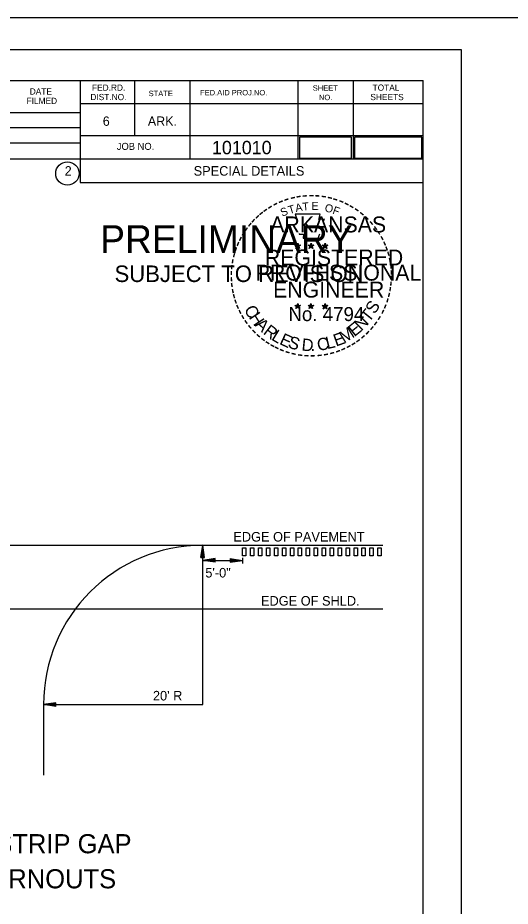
# Model space of a CAD drawing. Extents: x 3575 to 11445, y 9479 to 13278.
# Drawn here: x 8971 to 9280, y 10549 to 11106 of the extents above; entities that cross this region are included whole.
import ezdxf

# ---------------------------------------------------------------- set-up
doc = ezdxf.new("R2010")
doc.units = 0
for name, color, linetype in [('Page Number', 7, 'Continuous'), ('R_Dimension', 7, 'Continuous'), ('R_NoPlot', 7, 'Continuous'), ('STAMP_PE_CRAFTON-SIGNATURE', 7, 'Continuous'), ('STAMP_PE_FOSTER-SIGNATURE', 7, 'Continuous'), ('STAMP_PE_SEAL-INFO', 7, 'Continuous'), ('STAMP_PE_TAEGTMEYER', 7, 'Continuous'), ('STAMP_PRELIMINARY', 7, 'Continuous'), ('Total_Pages', 7, 'Continuous')]:
    doc.layers.add(name, color=color, linetype=linetype)

msp = doc.modelspace()

# ---------------------------------------------------------------- linework, layer by layer
at = {"layer": 'Page Number'}
msp.add_lwpolyline([(9147.9, 11018.05), (9180.55, 11018.05), (9180.55, 11031.25), (9147.9, 11031.25)], close=True, dxfattribs=at)
at = {"layer": 'R_Dimension'}
for p, q in [((9085.94, 10767.34), (9087.1, 10775.08)), ((9085.94, 10767.34), (9087.1, 10775.08)), ((9086.14, 10767.34), (9087.1, 10773.79)), ((9086.14, 10767.34), (9087.1, 10773.79)), ((9088.27, 10767.34), (9087.1, 10775.08)), ((9088.27, 10767.34), (9087.1, 10775.08)), ((9088.07, 10767.34), (9087.1, 10773.79)), ((9088.07, 10767.34), (9087.1, 10773.79)), ((9085.94, 10767.34), (9088.27, 10767.34)), ((9085.94, 10767.34), (9088.27, 10767.34)), ((9086.33, 10767.34), (9087.1, 10772.45)), ((9086.33, 10767.34), (9087.1, 10772.45)), ((9086.53, 10767.34), (9087.1, 10771.17)), ((9086.53, 10767.34), (9087.1, 10771.17)), ((9086.73, 10767.34), (9087.1, 10769.85)), ((9086.73, 10767.34), (9087.1, 10769.85)), ((9086.92, 10767.34), (9087.1, 10768.56)), ((9086.92, 10767.34), (9087.1, 10768.56)), ((9087.87, 10767.34), (9087.1, 10772.45)), ((9087.87, 10767.34), (9087.1, 10772.45)), ((9087.68, 10767.34), (9087.1, 10771.17)), ((9087.68, 10767.34), (9087.1, 10771.17)), ((9087.48, 10767.34), (9087.1, 10769.85)), ((9087.48, 10767.34), (9087.1, 10769.85)), ((9087.29, 10767.34), (9087.1, 10768.56)), ((9087.29, 10767.34), (9087.1, 10768.56)), ((9094.85, 10766.7), (9087.1, 10765.54)), ((9094.85, 10764.38), (9087.1, 10765.54)), ((9094.85, 10766.51), (9088.4, 10765.54)), ((9094.85, 10764.57), (9088.4, 10765.54)), ((9094.85, 10766.31), (9089.73, 10765.54)), ((9094.85, 10764.77), (9089.73, 10765.54)), ((9094.85, 10766.12), (9091.02, 10765.54)), ((9094.85, 10764.96), (9091.02, 10765.54)), ((9094.85, 10765.92), (9092.33, 10765.54)), ((9094.85, 10765.16), (9092.33, 10765.54)), ((9094.85, 10765.72), (9093.62, 10765.54)), ((9094.85, 10765.36), (9093.62, 10765.54)), ((9094.85, 10764.38), (9094.85, 10766.7)), ((9104.36, 10766.7), (9112.1, 10765.54)), ((9104.36, 10766.7), (9104.36, 10764.38)), ((9104.36, 10766.51), (9110.81, 10765.54)), ((9104.36, 10766.31), (9109.48, 10765.54)), ((9104.36, 10766.12), (9108.19, 10765.54)), ((9104.36, 10765.91), (9106.88, 10765.54)), ((9104.36, 10765.72), (9105.58, 10765.54)), ((9104.36, 10764.38), (9112.1, 10765.54)), ((9104.36, 10765.16), (9106.88, 10765.54)), ((9104.36, 10764.77), (9109.48, 10765.54)), ((9104.36, 10764.57), (9110.81, 10765.54)), ((9104.36, 10764.96), (9108.19, 10765.54)), ((9104.36, 10765.36), (9105.58, 10765.54)), ((8994.83, 10676.23), (8987.09, 10675.06)), ((8994.83, 10676.23), (8987.09, 10675.06)), ((8994.83, 10673.9), (8987.09, 10675.06)), ((8994.83, 10673.9), (8987.09, 10675.06)), ((8994.83, 10676.03), (8988.38, 10675.06)), ((8994.83, 10676.03), (8988.38, 10675.06)), ((8994.83, 10674.1), (8988.38, 10675.06)), ((8994.83, 10674.1), (8988.38, 10675.06)), ((8994.83, 10675.84), (8989.71, 10675.06)), ((8994.83, 10675.84), (8989.71, 10675.06)), ((8994.83, 10674.29), (8989.71, 10675.06)), ((8994.83, 10674.29), (8989.71, 10675.06)), ((8994.83, 10675.64), (8991, 10675.06)), ((8994.83, 10675.64), (8991, 10675.06)), ((8994.83, 10674.49), (8991, 10675.06)), ((8994.83, 10674.49), (8991, 10675.06)), ((8994.83, 10675.44), (8992.32, 10675.06)), ((8994.83, 10675.44), (8992.32, 10675.06)), ((8994.83, 10674.69), (8992.32, 10675.06)), ((8994.83, 10674.69), (8992.32, 10675.06)), ((8994.83, 10675.25), (8993.61, 10675.06)), ((8994.83, 10675.25), (8993.61, 10675.06)), ((8994.83, 10674.88), (8993.61, 10675.06)), ((8994.83, 10674.88), (8993.61, 10675.06)), ((8994.83, 10673.9), (8994.83, 10676.23)), ((8994.83, 10673.9), (8994.83, 10676.23))]:
    msp.add_line(p, q, dxfattribs=at)
at = {"layer": 'R_NoPlot'}
msp.add_lwpolyline([(7582.64, 11086.17), (9249.34, 11086.17), (9249.34, 10019.49), (7582.64, 10019.49)], close=True, dxfattribs=at)
at = {"layer": 'STAMP_PE_CRAFTON-SIGNATURE'}
for p, q in [((8686.88, 10775.08), (9200.28, 10775.08)), ((9087.1, 10675.06), (9087.1, 10775.08)), ((9112.1, 10767.26), (9112.1, 10763.56)), ((9087.1, 10765.54), (9112.1, 10765.54)), ((8686.88, 10735.07), (9200.28, 10735.07)), ((8987.09, 10675.06), (8987.09, 10630.78)), ((8987.09, 10675.06), (9087.1, 10675.06))]:
    msp.add_line(p, q, dxfattribs=at)
for points in [[(9112.1, 10768.41), (9112.1, 10773.41), (9114.19, 10773.41), (9114.19, 10768.41), (9112.1, 10768.41)], [(9117.1, 10768.41), (9117.1, 10773.41), (9119.19, 10773.41), (9119.19, 10768.41), (9117.1, 10768.41)], [(9122.1, 10768.41), (9122.1, 10773.41), (9124.19, 10773.41), (9124.19, 10768.41), (9122.1, 10768.41)], [(9127.1, 10768.41), (9127.1, 10773.41), (9129.19, 10773.41), (9129.19, 10768.41), (9127.1, 10768.41)], [(9132.1, 10768.41), (9132.1, 10773.41), (9134.19, 10773.41), (9134.19, 10768.41), (9132.1, 10768.41)], [(9137.1, 10768.41), (9137.1, 10773.41), (9139.19, 10773.41), (9139.19, 10768.41), (9137.1, 10768.41)], [(9142.11, 10768.41), (9142.11, 10773.41), (9144.19, 10773.41), (9144.19, 10768.41), (9142.11, 10768.41)], [(9147.11, 10768.41), (9147.11, 10773.41), (9149.19, 10773.41), (9149.19, 10768.41), (9147.11, 10768.41)], [(9152.11, 10768.41), (9152.11, 10773.41), (9154.19, 10773.41), (9154.19, 10768.41), (9152.11, 10768.41)], [(9157.11, 10768.41), (9157.11, 10773.41), (9159.19, 10773.41), (9159.19, 10768.41), (9157.11, 10768.41)], [(9162.11, 10768.41), (9162.11, 10773.41), (9164.19, 10773.41), (9164.19, 10768.41), (9162.11, 10768.41)], [(9167.11, 10768.41), (9167.11, 10773.41), (9169.19, 10773.41), (9169.19, 10768.41), (9167.11, 10768.41)], [(9172.11, 10768.41), (9172.11, 10773.41), (9174.19, 10773.41), (9174.19, 10768.41), (9172.11, 10768.41)], [(9177.11, 10768.41), (9177.11, 10773.41), (9179.19, 10773.41), (9179.19, 10768.41), (9177.11, 10768.41)], [(9182.11, 10768.41), (9182.11, 10773.41), (9184.19, 10773.41), (9184.19, 10768.41), (9182.11, 10768.41)], [(9187.11, 10768.41), (9187.11, 10773.41), (9189.19, 10773.41), (9189.19, 10768.41), (9187.11, 10768.41)], [(9192.11, 10768.41), (9192.11, 10773.41), (9194.19, 10773.41), (9194.19, 10768.41), (9192.11, 10768.41)], [(9197.11, 10768.41), (9197.11, 10773.41), (9199.19, 10773.41), (9199.19, 10768.41), (9197.11, 10768.41)]]:
    msp.add_lwpolyline(points, dxfattribs=at)
msp.add_arc((9087.1, 10675.06), 100.02, 90, 180, dxfattribs=at)
at = {"layer": 'STAMP_PE_FOSTER-SIGNATURE'}
for p, q in [((9144.99, 10963.44), (9146.73, 10962.89)), ((9144.99, 10963.44), (9146.25, 10963.22)), ((9144.99, 10963.44), (9146.17, 10962.83)), ((9145.65, 10961.4), (9146.73, 10962.89)), ((9145.65, 10961.4), (9146.28, 10962.62)), ((9145.65, 10961.4), (9146.72, 10962.49)), ((9146.73, 10964.71), (9146.53, 10963.45)), ((9147.8, 10961.4), (9146.72, 10962.47)), ((9146.73, 10962.89), (9146.73, 10964.71)), ((9146.73, 10964.71), (9146.98, 10963.46)), ((9148.47, 10963.44), (9146.73, 10962.89)), ((9147.8, 10961.4), (9146.73, 10962.89)), ((9148.47, 10963.44), (9147.04, 10963.2)), ((9147.8, 10961.4), (9147.11, 10962.86)), ((9148.47, 10963.44), (9147.45, 10962.93)), ((9153.34, 10963.44), (9155.08, 10962.89)), ((9153.34, 10963.44), (9154.6, 10963.22)), ((9153.34, 10963.44), (9154.52, 10962.83)), ((9154, 10961.4), (9155.08, 10962.89)), ((9154, 10961.4), (9154.63, 10962.62)), ((9154, 10961.4), (9155.07, 10962.49)), ((9155.08, 10964.71), (9154.88, 10963.45)), ((9156.15, 10961.4), (9155.07, 10962.47)), ((9155.08, 10962.89), (9155.08, 10964.71)), ((9155.08, 10964.71), (9155.33, 10963.46)), ((9156.82, 10963.44), (9155.08, 10962.89)), ((9156.15, 10961.4), (9155.08, 10962.89)), ((9156.82, 10963.44), (9155.39, 10963.2)), ((9156.15, 10961.4), (9155.46, 10962.86)), ((9156.82, 10963.44), (9155.8, 10962.93)), ((9162.16, 10963.38), (9163.9, 10962.83)), ((9162.16, 10963.38), (9163.42, 10963.16)), ((9162.16, 10963.38), (9163.34, 10962.77)), ((9162.82, 10961.34), (9163.9, 10962.83)), ((9162.82, 10961.34), (9163.45, 10962.56)), ((9162.82, 10961.34), (9163.89, 10962.43)), ((9163.9, 10964.65), (9163.7, 10963.39)), ((9164.97, 10961.34), (9163.89, 10962.41)), ((9163.9, 10962.83), (9163.9, 10964.65)), ((9163.9, 10964.65), (9164.15, 10963.4)), ((9165.64, 10963.38), (9163.9, 10962.83)), ((9164.97, 10961.34), (9163.9, 10962.83)), ((9165.64, 10963.38), (9164.21, 10963.14)), ((9164.97, 10961.34), (9164.28, 10962.8)), ((9165.64, 10963.38), (9164.62, 10962.87)), ((9144.97, 10925.58), (9146.71, 10925.02)), ((9144.97, 10925.58), (9146.23, 10925.35)), ((9144.97, 10925.58), (9146.15, 10924.97)), ((9145.63, 10923.54), (9146.71, 10925.02)), ((9145.63, 10923.54), (9146.26, 10924.76)), ((9145.63, 10923.54), (9146.7, 10924.62)), ((9146.71, 10926.85), (9146.51, 10925.59)), ((9147.78, 10923.54), (9146.7, 10924.61)), ((9146.71, 10925.02), (9146.71, 10926.85)), ((9146.71, 10926.85), (9146.96, 10925.6)), ((9148.45, 10925.58), (9146.71, 10925.02)), ((9147.78, 10923.54), (9146.71, 10925.02)), ((9148.45, 10925.58), (9147.02, 10925.33)), ((9147.78, 10923.54), (9147.09, 10924.99)), ((9148.45, 10925.58), (9147.43, 10925.07)), ((9153.31, 10925.58), (9155.06, 10925.02)), ((9153.31, 10925.58), (9154.58, 10925.35)), ((9153.31, 10925.58), (9154.5, 10924.97)), ((9153.98, 10923.54), (9155.06, 10925.02)), ((9153.98, 10923.54), (9154.61, 10924.76)), ((9153.98, 10923.54), (9155.05, 10924.62)), ((9155.06, 10926.85), (9154.85, 10925.59)), ((9156.12, 10923.54), (9155.05, 10924.61)), ((9155.06, 10925.02), (9155.06, 10926.85)), ((9155.06, 10926.85), (9155.3, 10925.6)), ((9156.79, 10925.58), (9155.06, 10925.02)), ((9156.12, 10923.54), (9155.06, 10925.02)), ((9156.79, 10925.58), (9155.36, 10925.33)), ((9156.12, 10923.54), (9155.44, 10924.99)), ((9156.79, 10925.58), (9155.77, 10925.07)), ((9162.15, 10925.53), (9163.89, 10924.97)), ((9162.15, 10925.53), (9163.41, 10925.3)), ((9162.15, 10925.53), (9163.33, 10924.92)), ((9162.81, 10923.49), (9163.89, 10924.97)), ((9162.81, 10923.49), (9163.44, 10924.71)), ((9162.81, 10923.49), (9163.88, 10924.57)), ((9163.89, 10926.8), (9163.69, 10925.54)), ((9164.96, 10923.49), (9163.88, 10924.56)), ((9163.89, 10924.97), (9163.89, 10926.8)), ((9163.89, 10926.8), (9164.14, 10925.55)), ((9165.63, 10925.53), (9163.89, 10924.97)), ((9164.96, 10923.49), (9163.89, 10924.97)), ((9165.63, 10925.53), (9164.2, 10925.28)), ((9164.96, 10923.49), (9164.27, 10924.94)), ((9165.63, 10925.53), (9164.61, 10925.02))]:
    msp.add_line(p, q, dxfattribs=at)
for points in [[(9145.19, 10982.83), (9146.54, 10978.7)], [(9162.75, 10978.22), (9163.46, 10979.64), (9160.03, 10979.52), (9160.77, 10982.83), (9145.19, 10982.83)], [(9147.65, 10970.72), (9147.65, 10970.28), (9150.47, 10970.19), (9150.2, 10967.82), (9159.55, 10967.82), (9160.55, 10970.5)], [(9146.73, 10964.71), (9147.8, 10961.4), (9144.99, 10963.44), (9148.47, 10963.44), (9145.65, 10961.4), (9146.73, 10964.71)], [(9155.08, 10964.71), (9156.15, 10961.4), (9153.34, 10963.44), (9156.82, 10963.44), (9154, 10961.4), (9155.08, 10964.71)], [(9163.9, 10964.65), (9164.97, 10961.34), (9162.16, 10963.38), (9165.64, 10963.38), (9162.82, 10961.34), (9163.9, 10964.65)], [(9146.71, 10926.85), (9147.78, 10923.54), (9144.97, 10925.58), (9148.45, 10925.58), (9145.63, 10923.54), (9146.71, 10926.85)], [(9155.06, 10926.85), (9156.12, 10923.54), (9153.31, 10925.58), (9156.79, 10925.58), (9153.98, 10923.54), (9155.06, 10926.85)], [(9163.89, 10926.8), (9164.96, 10923.49), (9162.15, 10925.53), (9165.63, 10925.53), (9162.81, 10923.49), (9163.89, 10926.8)]]:
    msp.add_lwpolyline(points, dxfattribs=at)
for centre, radius in [((9146.72, 10962.88), 0.861), ((9146.72, 10962.88), 0.723), ((9146.72, 10962.88), 0.579), ((9146.72, 10962.88), 0.495), ((9146.72, 10962.88), 0.374), ((9146.72, 10962.88), 0.248), ((9146.72, 10962.88), 0.148), ((9155.07, 10962.88), 0.861), ((9155.07, 10962.88), 0.723), ((9155.07, 10962.88), 0.579), ((9155.07, 10962.88), 0.495), ((9155.07, 10962.88), 0.374), ((9155.07, 10962.88), 0.248), ((9155.07, 10962.88), 0.148), ((9163.89, 10962.82), 0.861), ((9163.89, 10962.82), 0.723), ((9163.89, 10962.82), 0.579), ((9163.89, 10962.82), 0.495), ((9163.89, 10962.82), 0.374), ((9163.89, 10962.82), 0.248), ((9163.89, 10962.82), 0.148), ((9146.7, 10925.02), 0.861), ((9146.7, 10925.02), 0.723), ((9146.7, 10925.02), 0.579), ((9146.7, 10925.02), 0.495), ((9146.7, 10925.02), 0.374), ((9146.7, 10925.02), 0.248), ((9146.7, 10925.02), 0.148), ((9155.05, 10925.02), 0.861), ((9155.05, 10925.02), 0.723), ((9155.05, 10925.02), 0.579), ((9155.05, 10925.02), 0.495), ((9155.05, 10925.02), 0.374), ((9155.05, 10925.02), 0.248), ((9155.05, 10925.02), 0.148), ((9163.88, 10924.97), 0.861), ((9163.88, 10924.97), 0.723), ((9163.88, 10924.97), 0.579), ((9163.88, 10924.97), 0.495), ((9163.88, 10924.97), 0.374), ((9163.88, 10924.97), 0.248), ((9163.88, 10924.97), 0.148)]:
    msp.add_circle(centre, radius, dxfattribs=at)
at = {"layer": 'STAMP_PRELIMINARY'}
for p, q in [((9248.58, 11106.1), (7488.58, 11106.1)), ((10977.11, 11106.1), (9217.11, 11106.1)), ((7644.68, 11066.7), (9225.58, 11066.7)), ((9010.08, 11066.7), (9010.08, 11002.7)), ((9044.28, 11066.7), (9044.28, 11032)), ((9078.98, 11066.7), (9078.98, 11017.3)), ((9146.88, 11066.7), (9146.88, 11017.3)), ((9181.58, 11066.7), (9181.58, 11017.3)), ((9225.58, 10039.4), (9225.58, 11066.7)), ((9225.58, 11052), (9010.08, 11052)), ((9225.58, 11052.1), (9225.58, 11052.1)), ((8814.28, 11046.6), (9010.08, 11046.6)), ((8814.28, 11037.3), (9010.08, 11037.3)), ((9225.58, 11032), (9010.08, 11032)), ((8814.28, 11027.6), (9010.08, 11027.6)), ((9225.58, 11017.3), (8814.28, 11017.3)), ((9010.08, 11002.7), (9225.58, 11002.7))]:
    msp.add_line(p, q, dxfattribs=at)
msp.add_circle((9002.01, 11008.38), 7.33, dxfattribs=at)
at = {"layer": 'Total_Pages'}
msp.add_lwpolyline([(9182.4, 11018.05), (9224.76, 11018.05), (9224.76, 11031.25), (9182.4, 11031.25)], close=True, dxfattribs=at)

# ---------------------------------------------------------------- texts
at = {"layer": 'STAMP_PE_CRAFTON-SIGNATURE'}
for s, height, p in [('EDGE OF PAVEMENT', 6.0002, (9106.29, 10777.39)), ('5\'-0"', 6, (9088.69, 10754.82)), ('EDGE OF SHLD.', 6.0002, (9123.66, 10737.17)), ("20' R", 6, (9055.77, 10677.64)), ('DETAIL FOR RUMBLE STRIP GAP', 12.0003, (8786.44, 10581.75)), ('AT DRIVEWAY TURNOUTS', 12.0003, (8828.5, 10559.75))]:
    msp.add_text(s, height=height, dxfattribs=at).set_placement(p)
at = {"layer": 'STAMP_PE_FOSTER-SIGNATURE'}
for s, height, rotation, p in [('-', 8, 28.7918, (9132.6, 10985.54)), ('-', 8, 24.3072, (9135.76, 10987.12)), ('-', 8, 19.1761, (9138.93, 10988.47)), ('-', 8, 13.6302, (9142.68, 10989.67)), ('-', 8, 10.2193, (9146.07, 10990.48)), ('T', 5, 6.0228, (9149.91, 10984.96)), ('-', 8, 5.8968, (9149.72, 10991.03)), ('-', 8, 0.1862, (9153.58, 10991.39)), ('E', 5, 0.8323, (9155.44, 10985.51)), ('-', 8, 357.743, (9157.19, 10991.33)), ('-', 8, 352.1617, (9160.91, 10991.05)), ('-', 8, 347.2049, (9164.51, 10990.48)), ('-', 8, 342.3362, (9167.68, 10989.7)), ('-', 8, 337.8551, (9171.36, 10988.59)), ('-', 8, 334.1211, (9174.51, 10987.23)), ('-', 8, 38.9507, (9124.34, 10979.82)), ('-', 8, 36.2317, (9126.72, 10981.71)), ('-', 8, 34.0636, (9129.61, 10983.69)), ('S', 5, 21.594, (9136.97, 10981.22)), ('T', 5, 16.4036, (9141.54, 10982.88)), ('A', 5, 11.2132, (9145.67, 10984.13)), ('O', 5, 350.4515, (9163.46, 10984.46)), ('F', 5, 340.0707, (9168.23, 10983.32)), ('-', 8, 329.6409, (9177.41, 10985.82)), ('-', 8, 325.8627, (9180.62, 10984.01)), ('-', 8, 48.4231, (9119.94, 10975.35)), ('-', 8, 42.9622, (9122.18, 10977.74)), ('-', 8, 320.5297, (9183.67, 10981.88)), ('-', 8, 315.5786, (9186.67, 10979.44)), ('-', 8, 54.2325, (9115.86, 10970.08)), ('-', 8, 50.6142, (9117.92, 10972.92)), ('-', 8, 309.8797, (9189.51, 10976.69)), ('-', 8, 306.6522, (9192.14, 10973.68)), ('-', 8, 62.8713, (9112.67, 10964.38)), ('-', 8, 58.0706, (9114.23, 10967.45)), ('-', 7, 303.6753, (9194.57, 10970.84)), ('-', 8, 299.6684, (9196.16, 10967.81)), ('-', 8, 72.3945, (9110.28, 10958.17)), ('-', 8, 67.7743, (9111.37, 10961.32)), ('-', 8, 294.6628, (9197.78, 10964.75)), ('-', 8, 290.5728, (9199.07, 10961.86)), ('-', 8, 75.461, (9109.29, 10954.6)), ('-', 8, 285.1233, (9200.24, 10958.96)), ('-', 8, 85.1863, (9108.25, 10947.58)), ('-', 8, 81.2013, (9108.63, 10951.04)), ('-', 8, 280.5493, (9201.24, 10955.25)), ('-', 8, 276.5962, (9202.05, 10951.41)), ('-', 8, 89.0622, (9108.13, 10944.08)), ('-', 8, 274.3301, (9202.35, 10947.8)), ('-', 8, 94.1959, (9108.3, 10940.45)), ('-', 8, 263.5172, (9202.42, 10941.31)), ('-', 8, 269.9407, (9202.52, 10944.64)), ('-', 8, 98.9479, (9108.66, 10937.12)), ('-', 8, 101.7149, (9109.34, 10933.45)), ('-', 8, 260.9953, (9202.07, 10938.04)), ('-', 8, 105.4578, (9110.15, 10930.48)), ('-', 8, 109.0874, (9111.22, 10927.32)), ('-', 8, 255.7626, (9200.56, 10931.21)), ('-', 8, 255.7626, (9201.52, 10934.65)), ('-', 8, 114.0643, (9112.49, 10924.34)), ('C', 7.7, 296.9133, (9112.86, 10923.3)), ('T', 7.7, 51.5114, (9191.53, 10914.47)), ('S', 7.7, 57.878, (9195.17, 10919.68)), ('-', 8, 247.8887, (9199.5, 10927.69)), ('-', 8, 115.7289, (9114.02, 10921.25)), ('-', 8, 120.4471, (9115.8, 10918.32)), ('H', 7.7, 303.2799, (9115.81, 10918.1)), ('N', 7.7, 45.1449, (9186.73, 10909.26)), ('-', 8, 239.0712, (9196.22, 10920.78)), ('-', 8, 244.6197, (9198.19, 10924.54)), ('-', 8, 125.8934, (9117.82, 10915.52)), ('-', 8, 130.7181, (9120.13, 10912.76)), ('A', 7.7, 316.013, (9119.45, 10912.97)), ('R', 7.7, 322.3796, (9124.58, 10908.06)), ('M', 7.7, 32.4117, (9175.88, 10901.55)), ('E', 7.7, 38.7783, (9182.28, 10905.61)), ('-', 8, 231.2538, (9192.06, 10914.69)), ('-', 8, 233.8452, (9194.21, 10917.52)), ('-', 8, 134.2238, (9122.71, 10910.03)), ('-', 8, 138.9338, (9125.34, 10907.71)), ('L', 7.7, 328.7461, (9129.71, 10904.31)), ('E', 7.7, 335.1127, (9134.74, 10901.52)), ('E', 7.7, 19.6786, (9170.77, 10899.66)), ('-', 8, 221.0851, (9187.05, 10909.32)), ('-', 8, 225.7653, (9189.66, 10911.87)), ('-', 8, 144.6463, (9128.12, 10905.68)), ('-', 8, 148.0898, (9130.92, 10903.83)), ('-', 8, 151.5704, (9133.82, 10902.2)), ('S', 7.7, 341.4792, (9140.07, 10899.36)), ('D', 7.7, 354.2124, (9148.9, 10897.3)), ('C', 7.7, 6.9455, (9159.33, 10897.11)), ('L', 7.7, 13.3121, (9165.25, 10898.06)), ('-', 8, 212.2491, (9181.64, 10905.03)), ('-', 8, 215.7363, (9184.31, 10906.96)), ('-', 8, 154.6002, (9136.43, 10900.97)), ('-', 8, 158.5612, (9139.55, 10899.7)), ('-', 8, 162.7983, (9142.98, 10898.63)), ('-', 8, 167.5555, (9146.56, 10897.81)), ('.', 7.7, 0.5789, (9154.77, 10896.92)), ('-', 8, 191.2858, (9165.6, 10898.13)), ('-', 8, 195.4743, (9169.25, 10899.13)), ('-', 8, 200.7184, (9172.63, 10900.34)), ('-', 8, 204.2516, (9175.73, 10901.7)), ('-', 8, 207.3568, (9178.85, 10903.3)), ('-', 8, 173.1155, (9150.42, 10897.26)), ('-', 8, 176.5183, (9154.16, 10897)), ('-', 8, 181.5918, (9157.88, 10897.09)), ('-', 8, 185.8167, (9161.92, 10897.47))]:
    msp.add_text(s, height=height, rotation=rotation, dxfattribs=at).set_placement(p)
for s, height, p in [('ARKANSAS', 10, (9129.46, 10971.39)), ('REGISTERED', 10, (9126.07, 10950.65)), ('PROFESSIONAL', 10, (9120.33, 10941.13)), ('ENGINEER', 10, (9131.26, 10930.5)), ('No. 4794', 8.785, (9140.89, 10915.75))]:
    msp.add_text(s, height=height, dxfattribs=at).set_placement(p)
at = {"layer": 'STAMP_PE_SEAL-INFO'}
for s, height, p in [('PRELIMINARY', 17.5, (9022.61, 10958.41)), ('SUBJECT TO REVISION', 10.3756, (9031.65, 10940.26))]:
    msp.add_text(s, height=height, dxfattribs=at).set_placement(p)
at = {"layer": 'STAMP_PE_TAEGTMEYER'}
for s, height, p in [('101010', 8.4, (9092.85, 11020.45)), ('SPECIAL DETAILS', 6, (9081.35, 11007))]:
    msp.add_text(s, height=height, dxfattribs=at).set_placement(p)
at = {"layer": 'STAMP_PRELIMINARY'}
for s, height, p in [('FED.RD.', 3.91, (9017.48, 11060.3)), ('SHEET', 3.42, (9156.18, 11060.3)), ('TOTAL', 3.91, (9193.78, 11060.3)), ('DATE', 3.91, (8978.38, 11057.9)), ('DIST.NO.', 3.91, (9016.48, 11054.4)), ('STATE', 3.42, (9053.08, 11056.9)), ('FED.AID PROJ.NO.', 3.42, (9085.38, 11057.4)), ('NO.', 3.42, (9160.08, 11054.4)), ('SHEETS', 3.91, (9192.38, 11054.4)), ('FILMED', 3.91, (8976.38, 11052)), ('6', 5.86, (9024.28, 11038.3)), ('ARK.', 5.861, (9052.58, 11038.3)), ('JOB NO.', 4.396, (9033.08, 11023.2)), ('2', 5.86, (9000.38, 11007.1))]:
    msp.add_text(s, height=height, dxfattribs=at).set_placement(p)

doc.saveas('drawing.dxf')
